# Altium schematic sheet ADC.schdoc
size 297 x 209 mm; Symbol: Drawing-Symbol_A4; Company: 嘉立创EDA; Version: V1.0; Page Size: A4; @Project Name: 西柚在学EtherCAT; @Update Date: 2026-07-29; @Create Date: 2026-07-29; Device: Drawing-Symbol_A4; @Board Name: HPM5E3YIVK1; @Page Name: P7; @Create Time: 01:19:21; @Page Count: 7; @Page No: 7; @Schematic Name: HPM5E3YIVK1; @Update Time: 01:19:21; @Assembly Variant: Basic; Border: 1; Title Block Position: 3; Size: A4; Width: 1170; Height: 825; Region Start: 1; X Region Count: 6; Y Region Count: 4; Blade Width: 10
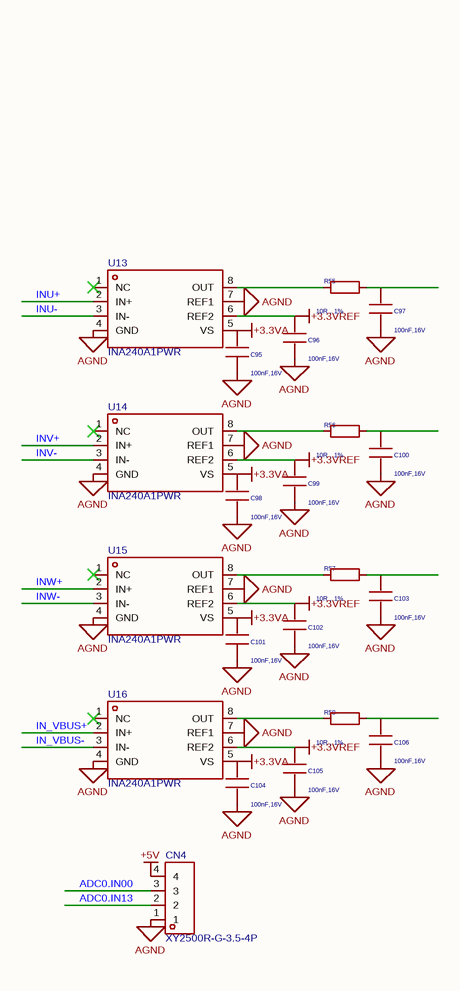
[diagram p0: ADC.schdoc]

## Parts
C95  value 100nF,16V  [03_HPM_Capacitance:C_0402_1005Metric]
C96  value 100nF,16V  [03_HPM_Capacitance:C_0402_1005Metric]
C97  value 100nF,16V  [03_HPM_Capacitance:C_0402_1005Metric]
C98  value 100nF,16V  [03_HPM_Capacitance:C_0402_1005Metric]
C99  value 100nF,16V  [03_HPM_Capacitance:C_0402_1005Metric]
C100  value 100nF,16V  [03_HPM_Capacitance:C_0402_1005Metric]
C101  value 100nF,16V  [03_HPM_Capacitance:C_0402_1005Metric]
C102  value 100nF,16V  [03_HPM_Capacitance:C_0402_1005Metric]
C103  value 100nF,16V  [03_HPM_Capacitance:C_0402_1005Metric]
C104  value 100nF,16V  [03_HPM_Capacitance:C_0402_1005Metric]
C105  value 100nF,16V  [03_HPM_Capacitance:C_0402_1005Metric]
C106  value 100nF,16V  [03_HPM_Capacitance:C_0402_1005Metric]
CN4  XY2500R-G-3.5-4P  [CONN-TH_XY2500R-G-3.5-4P]
R55  value 10R，1%  [02_HPM_Resistor:R_0402_1005Metric]
R56  value 10R，1%  [02_HPM_Resistor:R_0402_1005Metric]
R57  value 10R，1%  [02_HPM_Resistor:R_0402_1005Metric]
R58  value 10R，1%  [02_HPM_Resistor:R_0402_1005Metric]
U13  INA240A1PWR  [TSSOP-8_L4.4-W3.0-P0.65-LS6.4-BL]
U14  INA240A1PWR  [TSSOP-8_L4.4-W3.0-P0.65-LS6.4-BL]
U15  INA240A1PWR  [TSSOP-8_L4.4-W3.0-P0.65-LS6.4-BL]
U16  INA240A1PWR  [TSSOP-8_L4.4-W3.0-P0.65-LS6.4-BL]

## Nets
+3.3VA: C95.1 C98.1 C101.1 C104.1 U13.5(VS) U14.5(VS) U15.5(VS) U16.5(VS)
+3.3VREF: C96.1 C99.1 C102.1 C105.1 U13.6(REF2) U14.6(REF2) U15.6(REF2) U16.6(REF2)
+5V: CN4.4
AGND: C95.2 C96.2 C97.2 C98.2 C99.2 C100.2 C101.2 C102.2 C103.2 C104.2 C105.2 C106.2 CN4.1 U13.4(GND) U13.7(REF1) U14.4(GND) U14.7(REF1) U15.4(GND) U15.7(REF1) U16.4(GND) U16.7(REF1)
ADC0.IN00: CN4.3
ADC0.IN13: CN4.2
IN_VBUS+: U16.2(IN+)
IN_VBUS-: U16.3(IN-)
INU+: U13.2(IN+)
INU-: U13.3(IN-)
INV+: U14.2(IN+)
INV-: U14.3(IN-)
INW+: U15.2(IN+)
INW-: U15.3(IN-)
NetC97_1: C97.1 R55.1
NetC100_1: C100.1 R56.1
NetC103_1: C103.1 R57.1
NetC106_1: C106.1 R58.1
NetR55_2: R55.2 U13.8(OUT)
NetR56_2: R56.2 U14.8(OUT)
NetR57_2: R57.2 U15.8(OUT)
NetR58_2: R58.2 U16.8(OUT)

Not connected (* = marked no-connect by the designer): U13 1(NC)*; U14 1(NC)*; U15 1(NC)*; U16 1(NC)*

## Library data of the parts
C95 = 电容0402: Model: CL05B104KO5NNNC; Company: SAMSUNG(三星); ki_keywords: cap capacitor; ki_description: 0402; ki_fp_filters: C_*; ID: $1I27; 3D Model: 222a10e09e6e477a9f85628e277082cb0819f05c4eef4c71ace90d822a990e87; 3D Model Transform: 39.37,19.685,19.685,0,0,0,0,0,0; AddInBom: yes; UniqueId: gge83_22; ModelName: C0402
C96 = 电容0402: Model: CL05B104KO5NNNC; Company: SAMSUNG(三星); ki_keywords: cap capacitor; ki_description: 0402; ki_fp_filters: C_*; ID: $1I27; 3D Model: 222a10e09e6e477a9f85628e277082cb0819f05c4eef4c71ace90d822a990e87; 3D Model Transform: 39.37,19.685,19.685,0,0,0,0,0,0; AddInBom: yes; UniqueId: gge83_23; ModelName: C0402
C97 = 电容0402: Model: CL05B104KO5NNNC; Company: SAMSUNG(三星); ki_keywords: cap capacitor; ki_description: 0402; ki_fp_filters: C_*; ID: $1I27; 3D Model: 222a10e09e6e477a9f85628e277082cb0819f05c4eef4c71ace90d822a990e87; 3D Model Transform: 39.37,19.685,19.685,0,0,0,0,0,0; AddInBom: yes; UniqueId: gge83_24; ModelName: C0402
C98 = 电容0402: Model: CL05B104KO5NNNC; Company: SAMSUNG(三星); ki_keywords: cap capacitor; ki_description: 0402; ki_fp_filters: C_*; ID: $1I27; 3D Model: 222a10e09e6e477a9f85628e277082cb0819f05c4eef4c71ace90d822a990e87; 3D Model Transform: 39.37,19.685,19.685,0,0,0,0,0,0; AddInBom: yes; UniqueId: gge83_25; ModelName: C0402
C99 = 电容0402: Model: CL05B104KO5NNNC; Company: SAMSUNG(三星); ki_keywords: cap capacitor; ki_description: 0402; ki_fp_filters: C_*; ID: $1I27; 3D Model: 222a10e09e6e477a9f85628e277082cb0819f05c4eef4c71ace90d822a990e87; 3D Model Transform: 39.37,19.685,19.685,0,0,0,0,0,0; AddInBom: yes; UniqueId: gge83_26; ModelName: C0402
C100 = 电容0402: Model: CL05B104KO5NNNC; Company: SAMSUNG(三星); ki_keywords: cap capacitor; ki_description: 0402; ki_fp_filters: C_*; ID: $1I27; 3D Model: 222a10e09e6e477a9f85628e277082cb0819f05c4eef4c71ace90d822a990e87; 3D Model Transform: 39.37,19.685,19.685,0,0,0,0,0,0; AddInBom: yes; UniqueId: gge83_27; ModelName: C0402
C101 = 电容0402: Model: CL05B104KO5NNNC; Company: SAMSUNG(三星); ki_keywords: cap capacitor; ki_description: 0402; ki_fp_filters: C_*; ID: $1I27; 3D Model: 222a10e09e6e477a9f85628e277082cb0819f05c4eef4c71ace90d822a990e87; 3D Model Transform: 39.37,19.685,19.685,0,0,0,0,0,0; AddInBom: yes; UniqueId: gge83_28; ModelName: C0402
C102 = 电容0402: Model: CL05B104KO5NNNC; Company: SAMSUNG(三星); ki_keywords: cap capacitor; ki_description: 0402; ki_fp_filters: C_*; ID: $1I27; 3D Model: 222a10e09e6e477a9f85628e277082cb0819f05c4eef4c71ace90d822a990e87; 3D Model Transform: 39.37,19.685,19.685,0,0,0,0,0,0; AddInBom: yes; UniqueId: gge83_29; ModelName: C0402
C103 = 电容0402: Model: CL05B104KO5NNNC; Company: SAMSUNG(三星); ki_keywords: cap capacitor; ki_description: 0402; ki_fp_filters: C_*; ID: $1I27; 3D Model: 222a10e09e6e477a9f85628e277082cb0819f05c4eef4c71ace90d822a990e87; 3D Model Transform: 39.37,19.685,19.685,0,0,0,0,0,0; AddInBom: yes; UniqueId: gge83_30; ModelName: C0402
C104 = 电容0402: Model: CL05B104KO5NNNC; Company: SAMSUNG(三星); ki_keywords: cap capacitor; ki_description: 0402; ki_fp_filters: C_*; ID: $1I27; 3D Model: 222a10e09e6e477a9f85628e277082cb0819f05c4eef4c71ace90d822a990e87; 3D Model Transform: 39.37,19.685,19.685,0,0,0,0,0,0; AddInBom: yes; UniqueId: gge83_31; ModelName: C0402
C105 = 电容0402: Model: CL05B104KO5NNNC; Company: SAMSUNG(三星); ki_keywords: cap capacitor; ki_description: 0402; ki_fp_filters: C_*; ID: $1I27; 3D Model: 222a10e09e6e477a9f85628e277082cb0819f05c4eef4c71ace90d822a990e87; 3D Model Transform: 39.37,19.685,19.685,0,0,0,0,0,0; AddInBom: yes; UniqueId: gge83_32; ModelName: C0402
C106 = 电容0402: Model: CL05B104KO5NNNC; Company: SAMSUNG(三星); ki_keywords: cap capacitor; ki_description: 0402; ki_fp_filters: C_*; ID: $1I27; 3D Model: 222a10e09e6e477a9f85628e277082cb0819f05c4eef4c71ace90d822a990e87; 3D Model Transform: 39.37,19.685,19.685,0,0,0,0,0,0; AddInBom: yes; UniqueId: gge83_33; ModelName: C0402
CN4 = XY2500R-G-3.5-4P: 连接器类型:板端/插座-闭口;结构:1x4P;间距:3.5mm;颜色:绿色;安装方式:弯插;排数:1;每排PIN数:4;额定电流:8A;额定电压:300V;工作温度:-;; Manufacturer: XINLAIYA(新莱亚); 3D Model: 5c1021a19d22479eb9eb2320597402090819f05c4eef4c71ace90d822a990e87; 3D Model Transform: 590.55,358.267,0,0,0,0,0,-124.016,-137.795; Number of Positions or Pins: 1x4P; Pitch: 3.5mm; Number of PINs Per Row: 4; Current Rating: 8A; Voltage Rating (Max): 300V; AddInBom: yes
R55 = 电阻0402: Model: 0402WGF1002TCE; Company: UNI-ROYAL(厚声); ki_keywords: R res resistor; ki_description: Resistor; ki_fp_filters: R_*; ID: $3I57; 3D Model: 98c88bc2b9094f218f3a3e30a70127380819f05c4eef4c71ace90d822a990e87; 3D Model Transform: 39.37,19.685,14.173200563192367,0,0,0,0,0,0; AddInBom: yes; UniqueId: 469542c170a520e3_35; ModelName: R0402_L1.0-W0.5-H0.4
R56 = 电阻0402: Model: 0402WGF1002TCE; Company: UNI-ROYAL(厚声); ki_keywords: R res resistor; ki_description: Resistor; ki_fp_filters: R_*; ID: $3I57; 3D Model: 98c88bc2b9094f218f3a3e30a70127380819f05c4eef4c71ace90d822a990e87; 3D Model Transform: 39.37,19.685,14.173200563192367,0,0,0,0,0,0; AddInBom: yes; UniqueId: 469542c170a520e3_36; ModelName: R0402_L1.0-W0.5-H0.4
R57 = 电阻0402: Model: 0402WGF1002TCE; Company: UNI-ROYAL(厚声); ki_keywords: R res resistor; ki_description: Resistor; ki_fp_filters: R_*; ID: $3I57; 3D Model: 98c88bc2b9094f218f3a3e30a70127380819f05c4eef4c71ace90d822a990e87; 3D Model Transform: 39.37,19.685,14.173200563192367,0,0,0,0,0,0; AddInBom: yes; UniqueId: 469542c170a520e3_37; ModelName: R0402_L1.0-W0.5-H0.4
R58 = 电阻0402: Model: 0402WGF1002TCE; Company: UNI-ROYAL(厚声); ki_keywords: R res resistor; ki_description: Resistor; ki_fp_filters: R_*; ID: $3I57; 3D Model: 98c88bc2b9094f218f3a3e30a70127380819f05c4eef4c71ace90d822a990e87; 3D Model Transform: 39.37,19.685,14.173200563192367,0,0,0,0,0,0; AddInBom: yes; UniqueId: 469542c170a520e3_38; ModelName: R0402_L1.0-W0.5-H0.4
U13-U16 = INA240A1PWR: 放大器数:单路;共模电压:-4V~80V;增益:20V/V;带宽:400kHz;; Manufacturer: TI(德州仪器); AddInBom: yes; ModelId: 85577802f9634e7e85ffa2fd25a37b6f0819f05c4eef4c71ace90d822a990e87; ModelName: TSSOP-8_L4.4-W3.0-P0.65-LS6.4-BL-2; ModelTransform: 118.11,251.968,0,0,0,0,0,0,0; Number of Channels: 单路; Gain: 20V/V; Bandwidth: 400kHz; Ib - Input Bias Current: 90uA; Vos - Input Offset Voltage: 5uV; Differential Voltage: -80V~+80V; Maximum Power Supply Range (Vdd-Vss): 5.5V; Single Supply: 2.7V~5.5V; Quiescent Current: 1.8mA; Input Offset Voltage Drift(Vos TC): 250nV/℃; Slew Rate: 2V/us; Common Mode Rejection Ratio (CMRR): 132dB; Noise density(eN): 40nV/√Hz@1kHz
